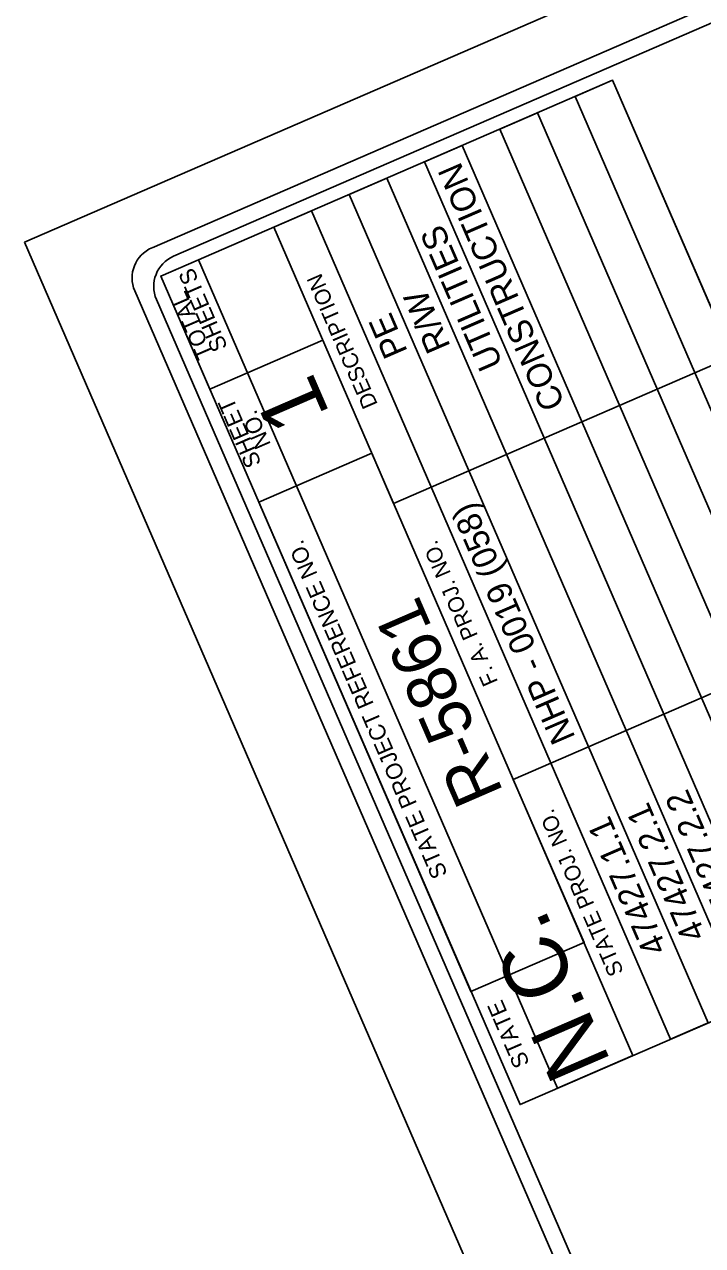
# Model space of a CAD drawing. Extents: x 442728 to 492797, y 479541 to 511293.
# Drawn here: x 465175 to 468274, y 500146 to 505724 of the extents above; entities that cross this region are included whole.
import ezdxf

# ---------------------------------------------------------------- set-up
doc = ezdxf.new("R2010")
doc.units = 0
for name, color, linetype in [('Sheet Data Field CELL', 7, 'Continuous'), ('Sheet Plot Border Outside CELL', 7, 'Continuous'), ('Sheet Title CELL', 7, 'Continuous')]:
    doc.layers.add(name, color=color, linetype=linetype)

msp = doc.modelspace()

# ---------------------------------------------------------------- linework, layer by layer
at = {"layer": 'Sheet Plot Border Outside CELL'}
msp.add_lwpolyline([(465175.4, 504729.3), (475224.7, 481554), (490362.8, 488118.1), (480313.5, 511293.4)], close=True, dxfattribs=at)
at = {"layer": 'Sheet Title CELL'}
for points in [[(479933.3, 510850.6), (465758.6, 504704.2)], [(477348.5, 509648.1), (465857, 504665.1)], [(468957, 502946.2), (467408.7, 502274.9), (467731.9, 501529.7), (467215.6, 501305.8), (466246, 503542.4), (466762, 503765.9), (466861.6, 503536.1), (468409.9, 504207.4), (467862.6, 505469.4), (465798.3, 504574.3), (466022.1, 504058.2), (466538.1, 504282.2)], [(469503.7, 501684.8), (467862.6, 505469.4), (467690.8, 505394.9), (469331.7, 501610.2)], [(469159.8, 501535.7), (467518.8, 505320.3), (467346.7, 505245.7), (468987.7, 501461.3)], [(468815.6, 501386.5), (467174.5, 505171), (467002.5, 505096.4), (468643.6, 501311.9)], [(468471.7, 501237.4), (466830.5, 505021.8), (466658.6, 504947.3), (468299.7, 501162.8), (468127.7, 501088.2), (466486.6, 504872.7), (466314.4, 504798.1), (467955.5, 501013.5), (467611.4, 500864.3), (465970.4, 504648.9), (465798.3, 504574.3), (467439.6, 500789.8), (469503.7, 501684.8)], [(465680.5, 504507.1), (474512.4, 484138.8)], [(465779.3, 504467.9), (474253, 484926)]]:
    msp.add_lwpolyline(points, dxfattribs=at)
for centre in [(465817.4, 504566.3), (465916.1, 504527.3)]:
    msp.add_arc(centre, 150, 113.4424, 203.4424, dxfattribs=at)

# ---------------------------------------------------------------- texts
at = {"layer": 'Sheet Data Field CELL'}
for s, height, p in [('CONSTRUCTION', 112.501, (467646.4, 503990.4)), ('UTILITIES', 112.5, (467362.9, 504172.9)), (' R/W', 112.5, (467140.1, 504215.6)), ('PE', 112.5, (466927.8, 504230.5)), ('NHP - 0019 (058)', 112.501, (467693.9, 502467.4)), ('R-5861', 225, (467365.4, 502216.5)), ('47427.2.2', 112.5, (468468.8, 501623.3)), ('47427.2.1', 112.5, (468290.3, 501563.4)), ('47427.1.1', 112.5, (468112.9, 501501.2))]:
    msp.add_text(s, height=height, rotation=113.4424, dxfattribs=at).set_placement(p)
at = {"layer": 'Sheet Title CELL'}
for s, height, p in [('SHEETS', 75, (466105.2, 504249.3)), ('DESCRIPTION', 72.001, (466790.7, 503988.5)), ('TOTAL', 75, (466038.4, 504214.9)), ('1', 290.3, (466573.1, 503943.2)), ('SHEET', 75, (466259.4, 503718.8)), ('NO.', 75, (466302.6, 503805.4)), ('STATE PROJECT REFERENCE NO.', 74.998, (467110, 501842)), ('F. A. PROJ. NO.', 72.001, (467340.2, 502720.9)), ('STATE PROJ. NO.', 72.001, (467914.8, 501395.6)), ('N.C.', 290.25, (467856.7, 500982.9)), ('STATE', 75, (467484.9, 500977))]:
    msp.add_text(s, height=height, rotation=113.4424, dxfattribs=at).set_placement(p)

doc.saveas('drawing.dxf')
